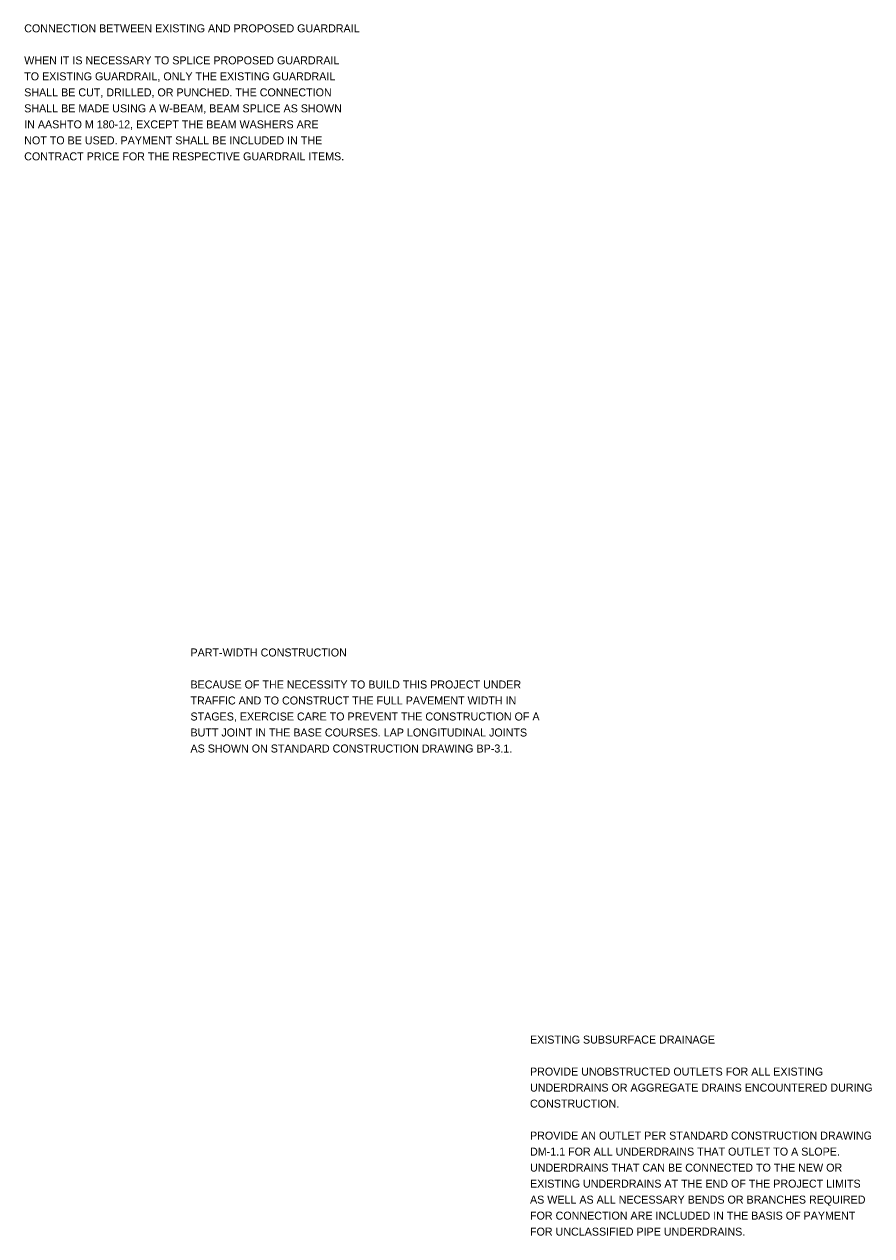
# Model space of a CAD drawing. Extents: x -14.3 to 49.6, y -18.9 to 35.3.
# Drawn here: x 34.53 to 49.35, y -0.06 to 21.14 of the extents above; entities that cross this region are included whole.
import ezdxf

# ---------------------------------------------------------------- set-up
doc = ezdxf.new("R2010")
doc.units = 0
doc.layers.add('SH_Text', color=7, linetype='Continuous')

msp = doc.modelspace()

# ---------------------------------------------------------------- texts
at = {"layer": 'SH_Text'}
for s, p in [('CONNECTION BETWEEN EXISTING AND PROPOSED GUARDRAIL', (34.526, 21)), ('WHEN IT IS NECESSARY TO SPLICE PROPOSED GUARDRAIL', (34.526, 20.44)), ('TO EXISTING GUARDRAIL, ONLY THE EXISTING GUARDRAIL', (34.526, 20.16)), ('SHALL BE CUT, DRILLED, OR PUNCHED. THE CONNECTION', (34.526, 19.88)), ('SHALL BE MADE USING A W-BEAM, BEAM SPLICE AS SHOWN', (34.526, 19.6)), ('IN AASHTO M 180-12, EXCEPT THE BEAM WASHERS ARE', (34.526, 19.32)), ('NOT TO BE USED. PAYMENT SHALL BE INCLUDED IN THE', (34.526, 19.04)), ('CONTRACT PRICE FOR THE RESPECTIVE GUARDRAIL ITEMS.', (34.526, 18.76)), ('PART-WIDTH CONSTRUCTION', (37.434, 10.08)), ('BECAUSE OF THE NECESSITY TO BUILD THIS PROJECT UNDER', (37.434, 9.52)), ('TRAFFIC AND TO CONSTRUCT THE FULL PAVEMENT WIDTH IN', (37.434, 9.24)), ('STAGES, EXERCISE CARE TO PREVENT THE CONSTRUCTION OF A', (37.434, 8.96)), ('BUTT JOINT IN THE BASE COURSES. LAP LONGITUDINAL JOINTS', (37.434, 8.68)), ('AS SHOWN ON STANDARD CONSTRUCTION DRAWING BP-3.1.', (37.434, 8.4)), ('EXISTING SUBSURFACE DRAINAGE', (43.373, 3.307)), ('PROVIDE UNOBSTRUCTED OUTLETS FOR ALL EXISTING', (43.373, 2.747)), ('UNDERDRAINS OR AGGREGATE DRAINS ENCOUNTERED DURING', (43.373, 2.467)), ('CONSTRUCTION.', (43.373, 2.187)), ('PROVIDE AN OUTLET PER STANDARD CONSTRUCTION DRAWING', (43.373, 1.627)), ('DM-1.1 FOR ALL UNDERDRAINS THAT OUTLET TO A SLOPE.', (43.373, 1.347)), ('UNDERDRAINS THAT CAN BE CONNECTED TO THE NEW OR', (43.373, 1.067)), ('EXISTING UNDERDRAINS AT THE END OF THE PROJECT LIMITS', (43.373, 0.787)), ('AS WELL AS ALL NECESSARY BENDS OR BRANCHES REQUIRED', (43.373, 0.507)), ('FOR CONNECTION ARE INCLUDED IN THE BASIS OF PAYMENT', (43.373, 0.227)), ('FOR UNCLASSIFIED PIPE UNDERDRAINS.', (43.373, -0.053))]:
    msp.add_text(s, height=0.14, dxfattribs=at).set_placement(p)

doc.saveas('drawing.dxf')
